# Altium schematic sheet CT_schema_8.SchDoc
size 308 x 210 mm
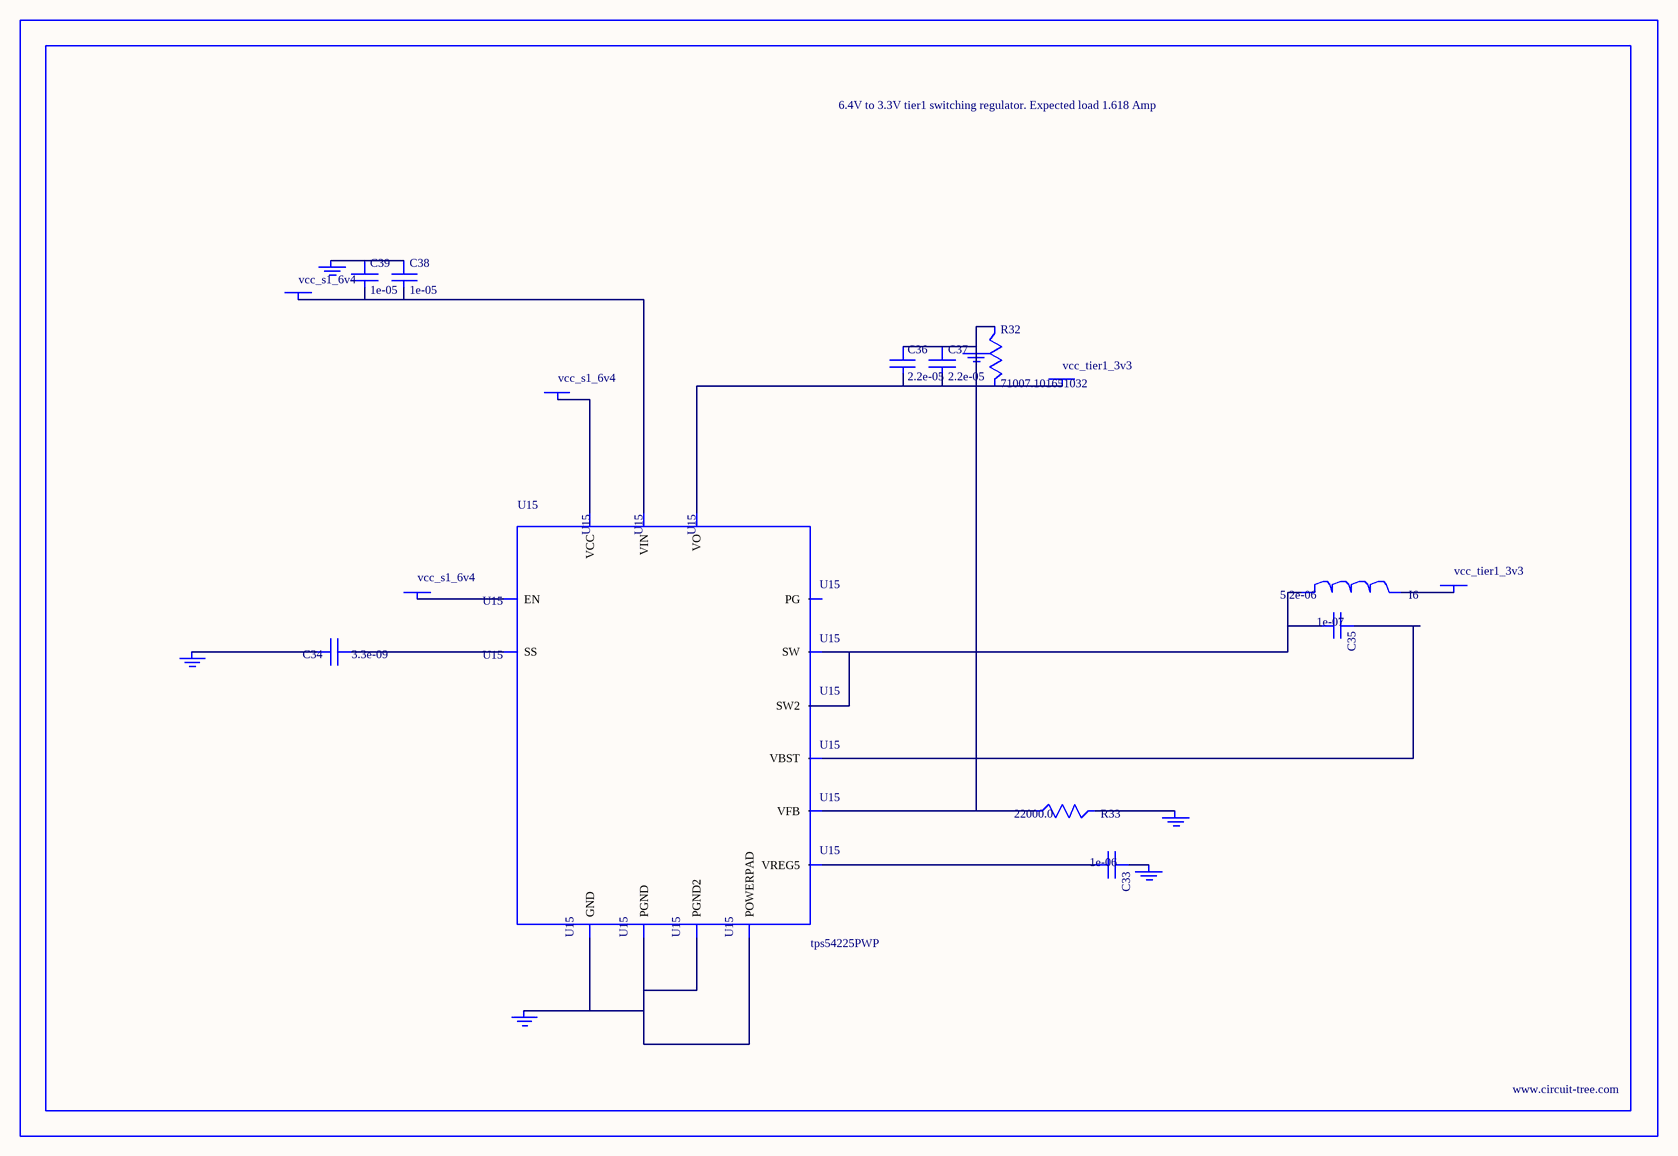
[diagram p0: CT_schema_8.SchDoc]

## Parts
BORDER7  (no value)
C33  1e-06  [C0603]
C34  3.3e-09  [C0402]
C35  1e-07  [C0402]
C36  2.2e-05  [C1210]
C37  2.2e-05  [C1210]
C38  1e-05  [C0805]
C39  1e-05  [C0805]
GND_INSTANCE_7_0  (no value)
GND_INSTANCE_7_1  (no value)
GND_INSTANCE_7_2  (no value)
GND_INSTANCE_7_3  (no value)
GND_INSTANCE_7_4  (no value)
GND_INSTANCE_7_5  (no value)
I6  5.2e-06  [DR1040]
POWER_INSTANCE_7_0  vcc_tier1_3v3
POWER_INSTANCE_7_1  vcc_s1_6v4
POWER_INSTANCE_7_2  vcc_tier1_3v3
POWER_INSTANCE_7_3  vcc_s1_6v4
POWER_INSTANCE_7_4  vcc_s1_6v4
R32  71007.101651032  [R0603]
R33  22000.0  [R0603]
U15  tps54225PWP  [HTSSOP14]

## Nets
NetC33_1: C33.1 GND_INSTANCE_7_2.0(GND)
NetC33_2: C33.2 U15.3(VREG5)
NetC34_1: C34.1 U15.4(SS)
NetC34_2: C34.2 GND_INSTANCE_7_3.0(GND)
NetC35_1: C35.1 U15.12(VBST)
NetC35_2: C35.2 I6.1 U15.10(SW) U15.11(SW2)
NetC36_1: C36.1 C37.1 GND_INSTANCE_7_0.0(GND) R32.1 R33.1 U15.2(VFB)
NetC36_2: C36.2 C37.2 POWER_INSTANCE_7_0.0(PWR) R32.2 U15.1(VO)
NetC38_1: C38.1 C39.1 GND_INSTANCE_7_5.0(GND)
NetC38_2: C38.2 C39.2 POWER_INSTANCE_7_3.0(PWR) U15.13(VIN)
NetGND_INSTANCE_7_1_0: GND_INSTANCE_7_1.0(GND) R33.2
NetGND_INSTANCE_7_4_0: GND_INSTANCE_7_4.0(GND) U15.5(GND) U15.8(PGND) U15.9(PGND2) U15.15(POWERPAD)
NetI6_2: I6.2 POWER_INSTANCE_7_2.0(PWR)
NetPOWER_INSTANCE_7_1_0: POWER_INSTANCE_7_1.0(PWR) U15.7(EN)
NetPOWER_INSTANCE_7_4_0: POWER_INSTANCE_7_4.0(PWR) U15.14(VCC)

Not connected (* = marked no-connect by the designer): U15 6(PG)

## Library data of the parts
BORDER7 = BORDER_PAGE7
C33 = C0603C105K3RACTU
C34 = C0402C332K3RAC
C35 = C0402C104K3RACTU
C36 C37 = GRM32ER61E226ME15L
C38 C39 = C0805C106K8RACTU
GND_INSTANCE_7_0-GND_INSTANCE_7_5 = GND
I6 = DR1040-5R2-R
POWER_INSTANCE_7_0-POWER_INSTANCE_7_4 = PWR
R32 = R32
R33 = RC0603JR-0722KL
